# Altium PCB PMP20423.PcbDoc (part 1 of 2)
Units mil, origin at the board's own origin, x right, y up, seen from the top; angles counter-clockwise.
Board outline 2175 x 2115 mil, 4 copper layers (Top Layer, Signal Layer 1, Signal Layer 2, Bottom Layer), stack 82.634 mil thick; 73 components, 45 nets, 246 pads, 105 vias.
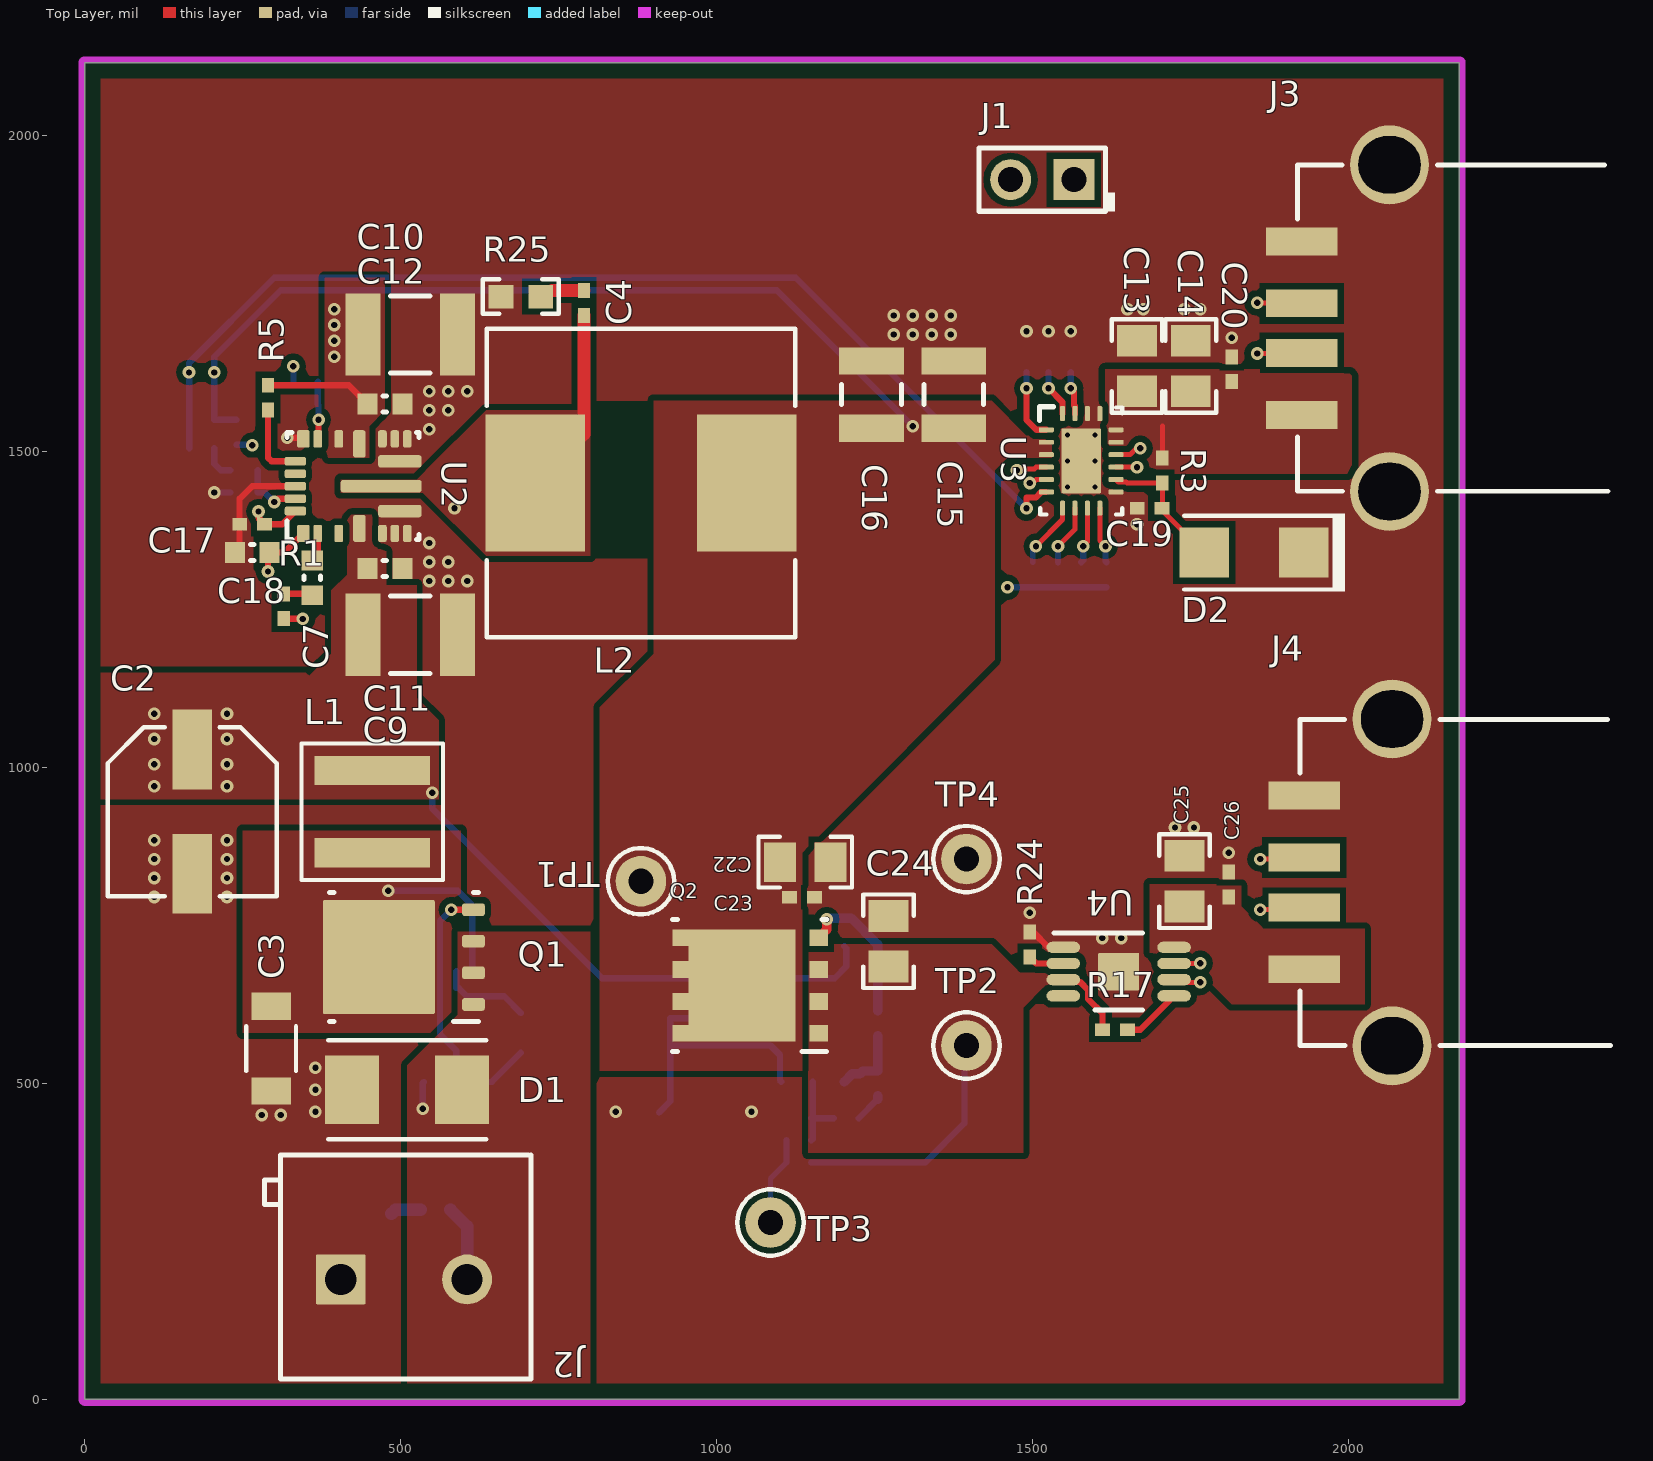
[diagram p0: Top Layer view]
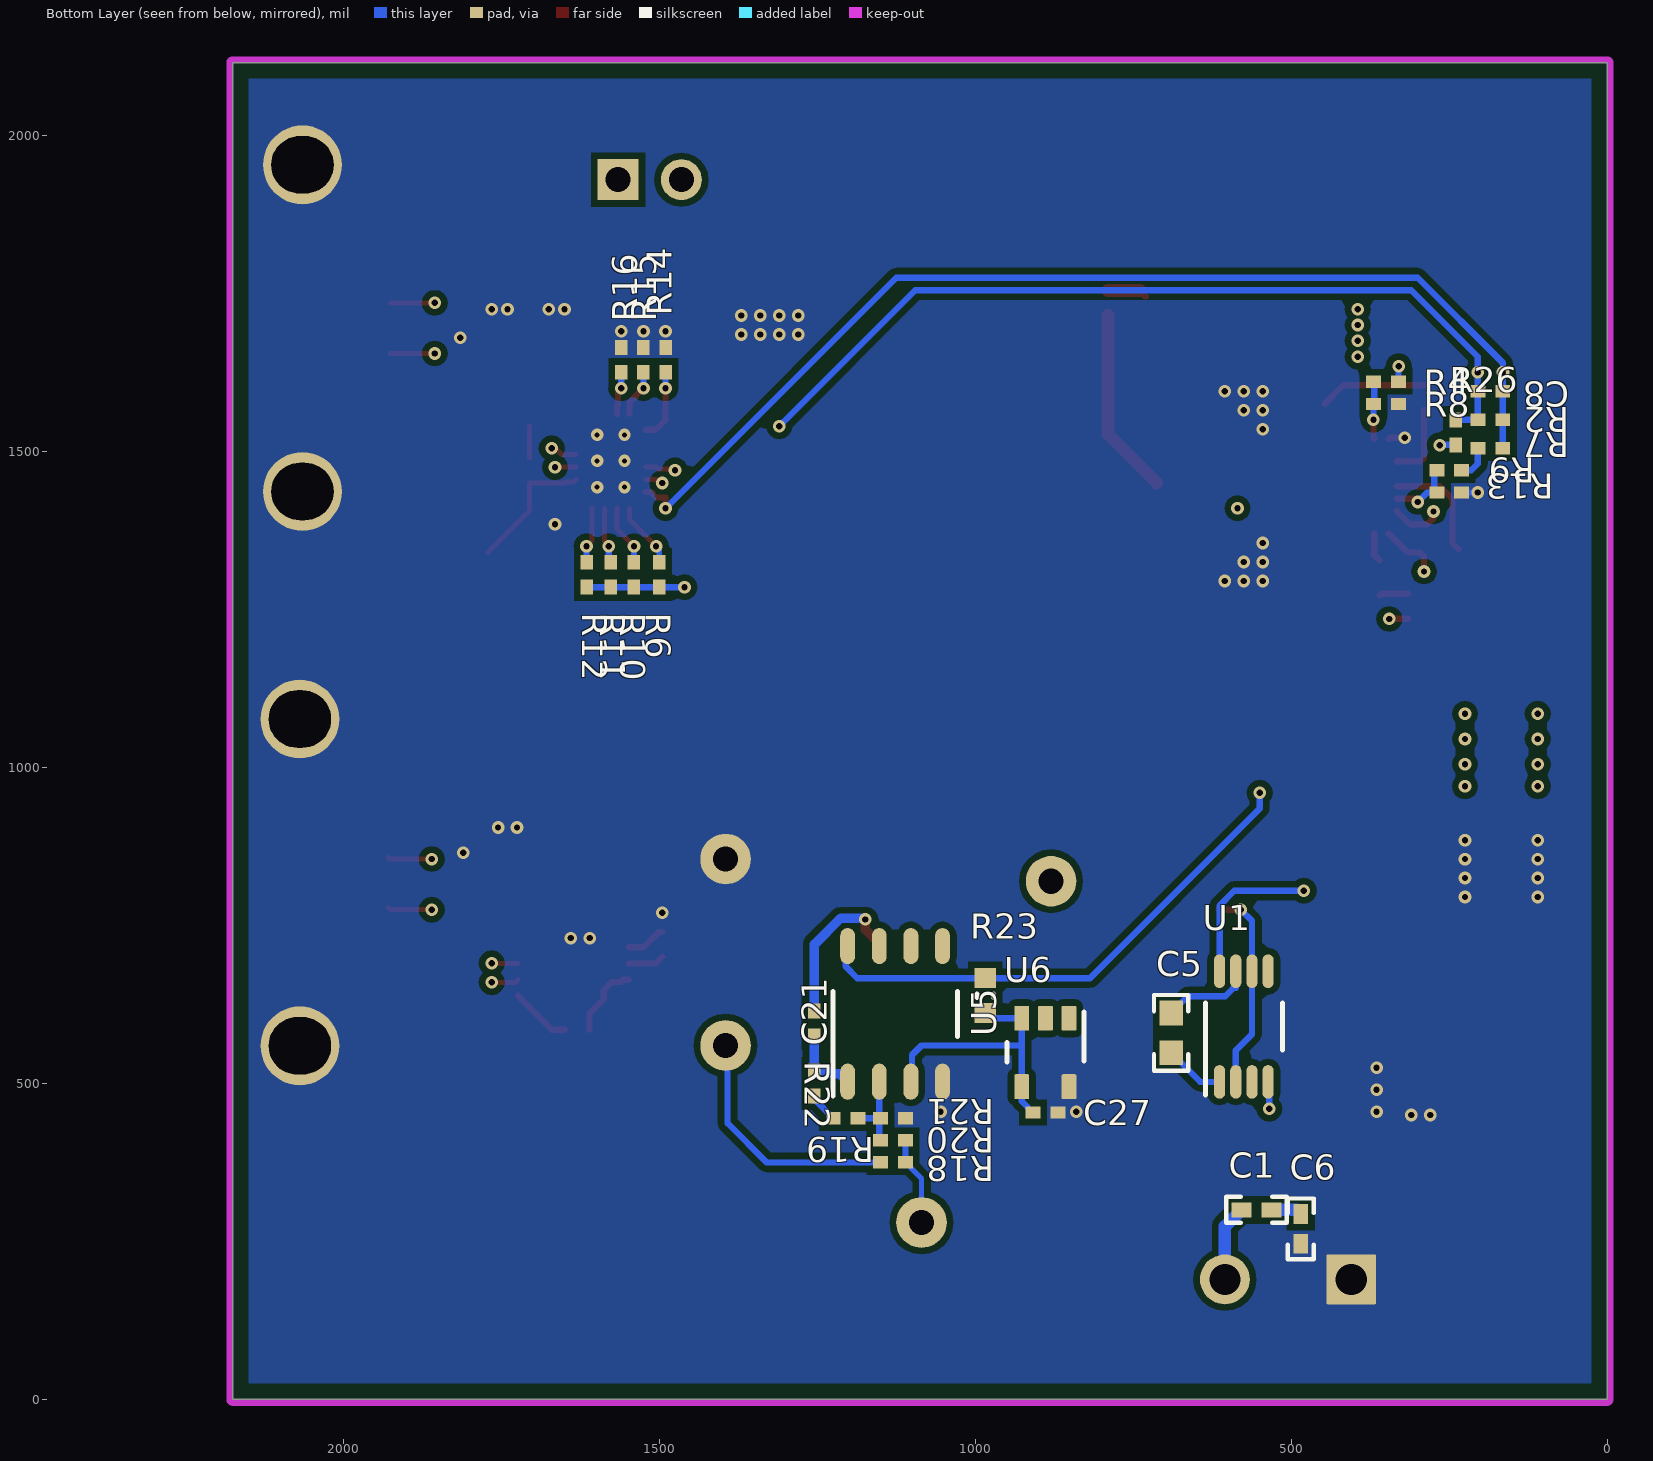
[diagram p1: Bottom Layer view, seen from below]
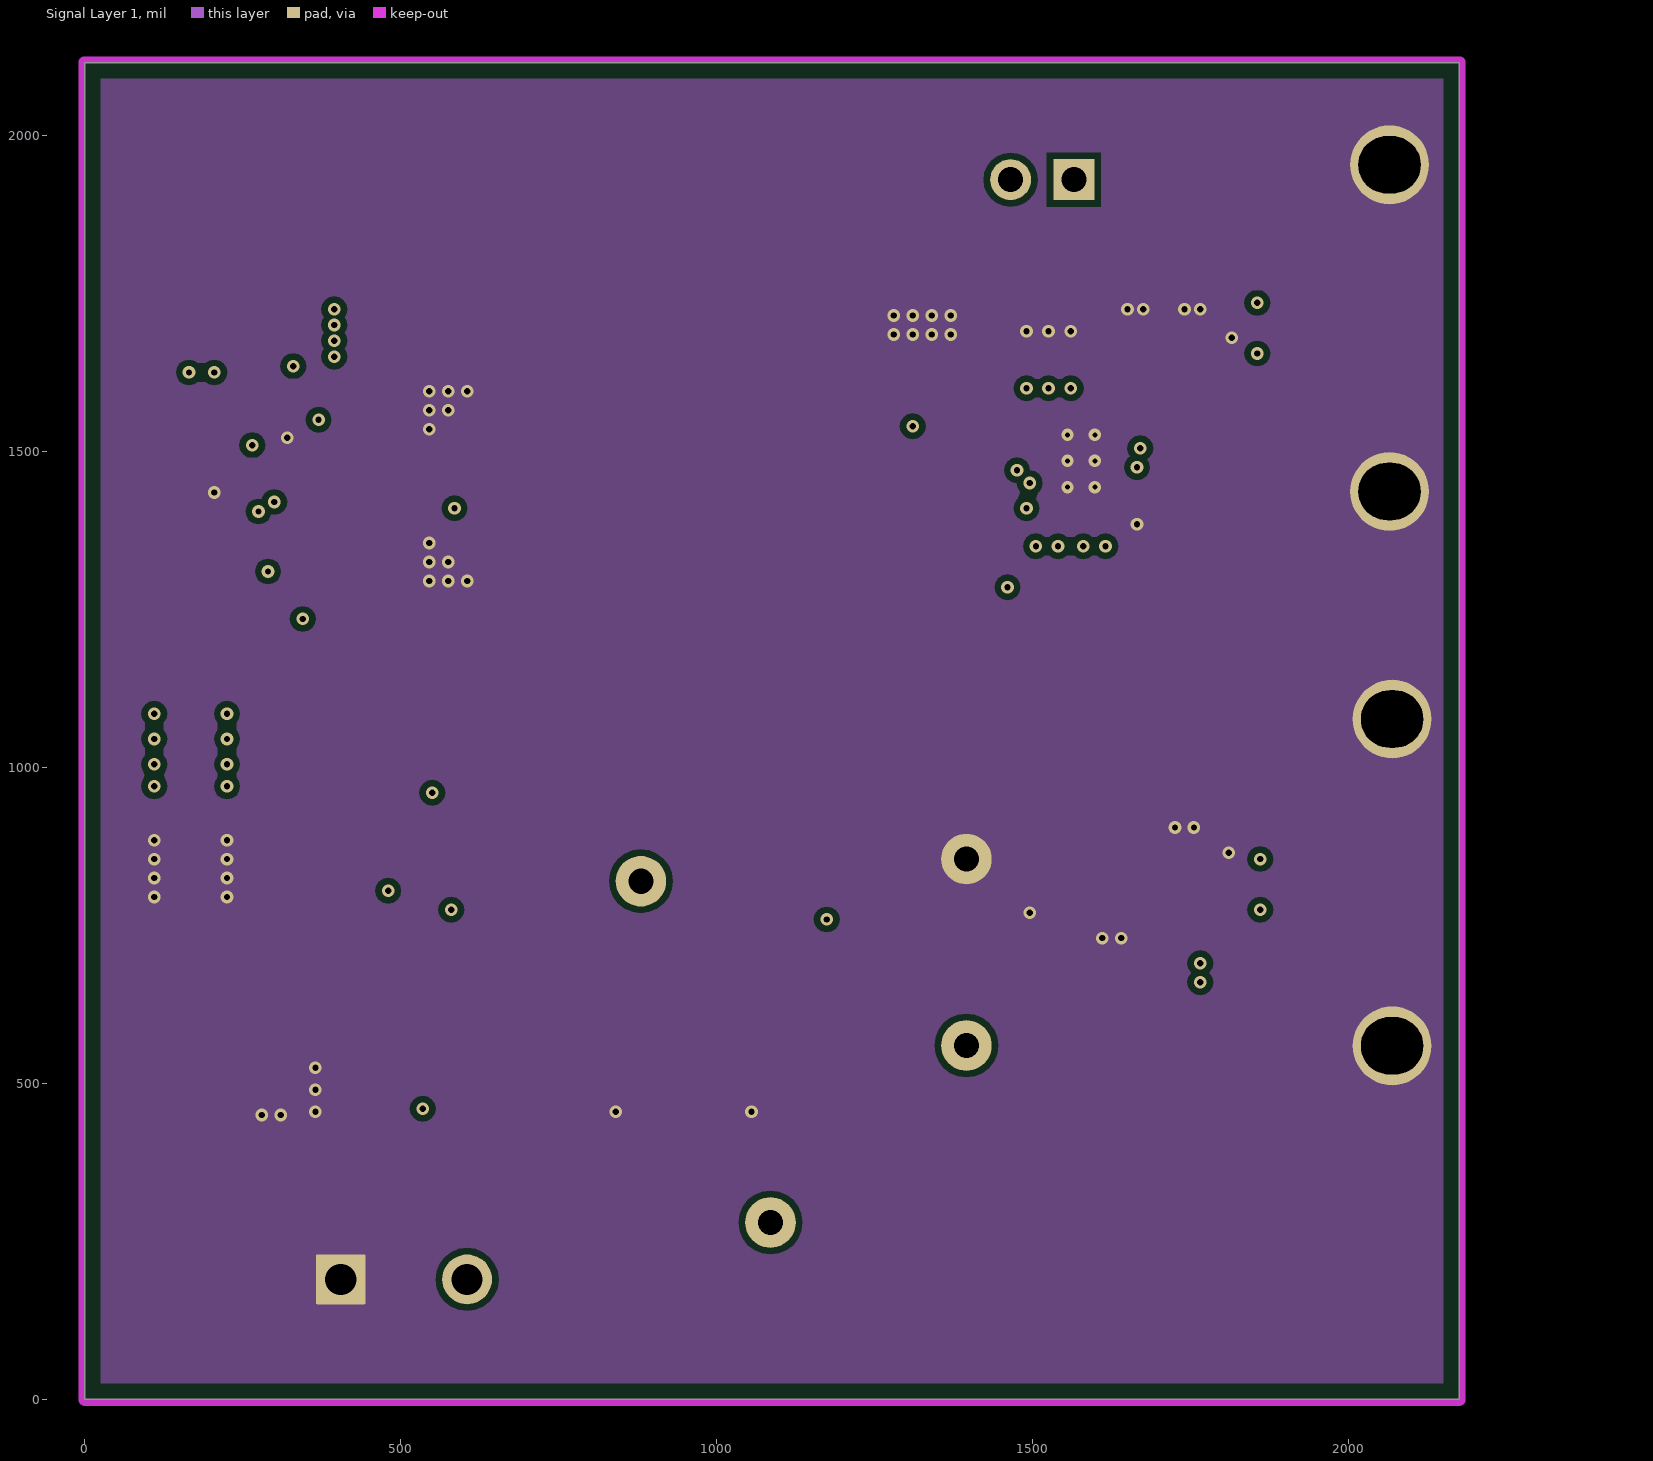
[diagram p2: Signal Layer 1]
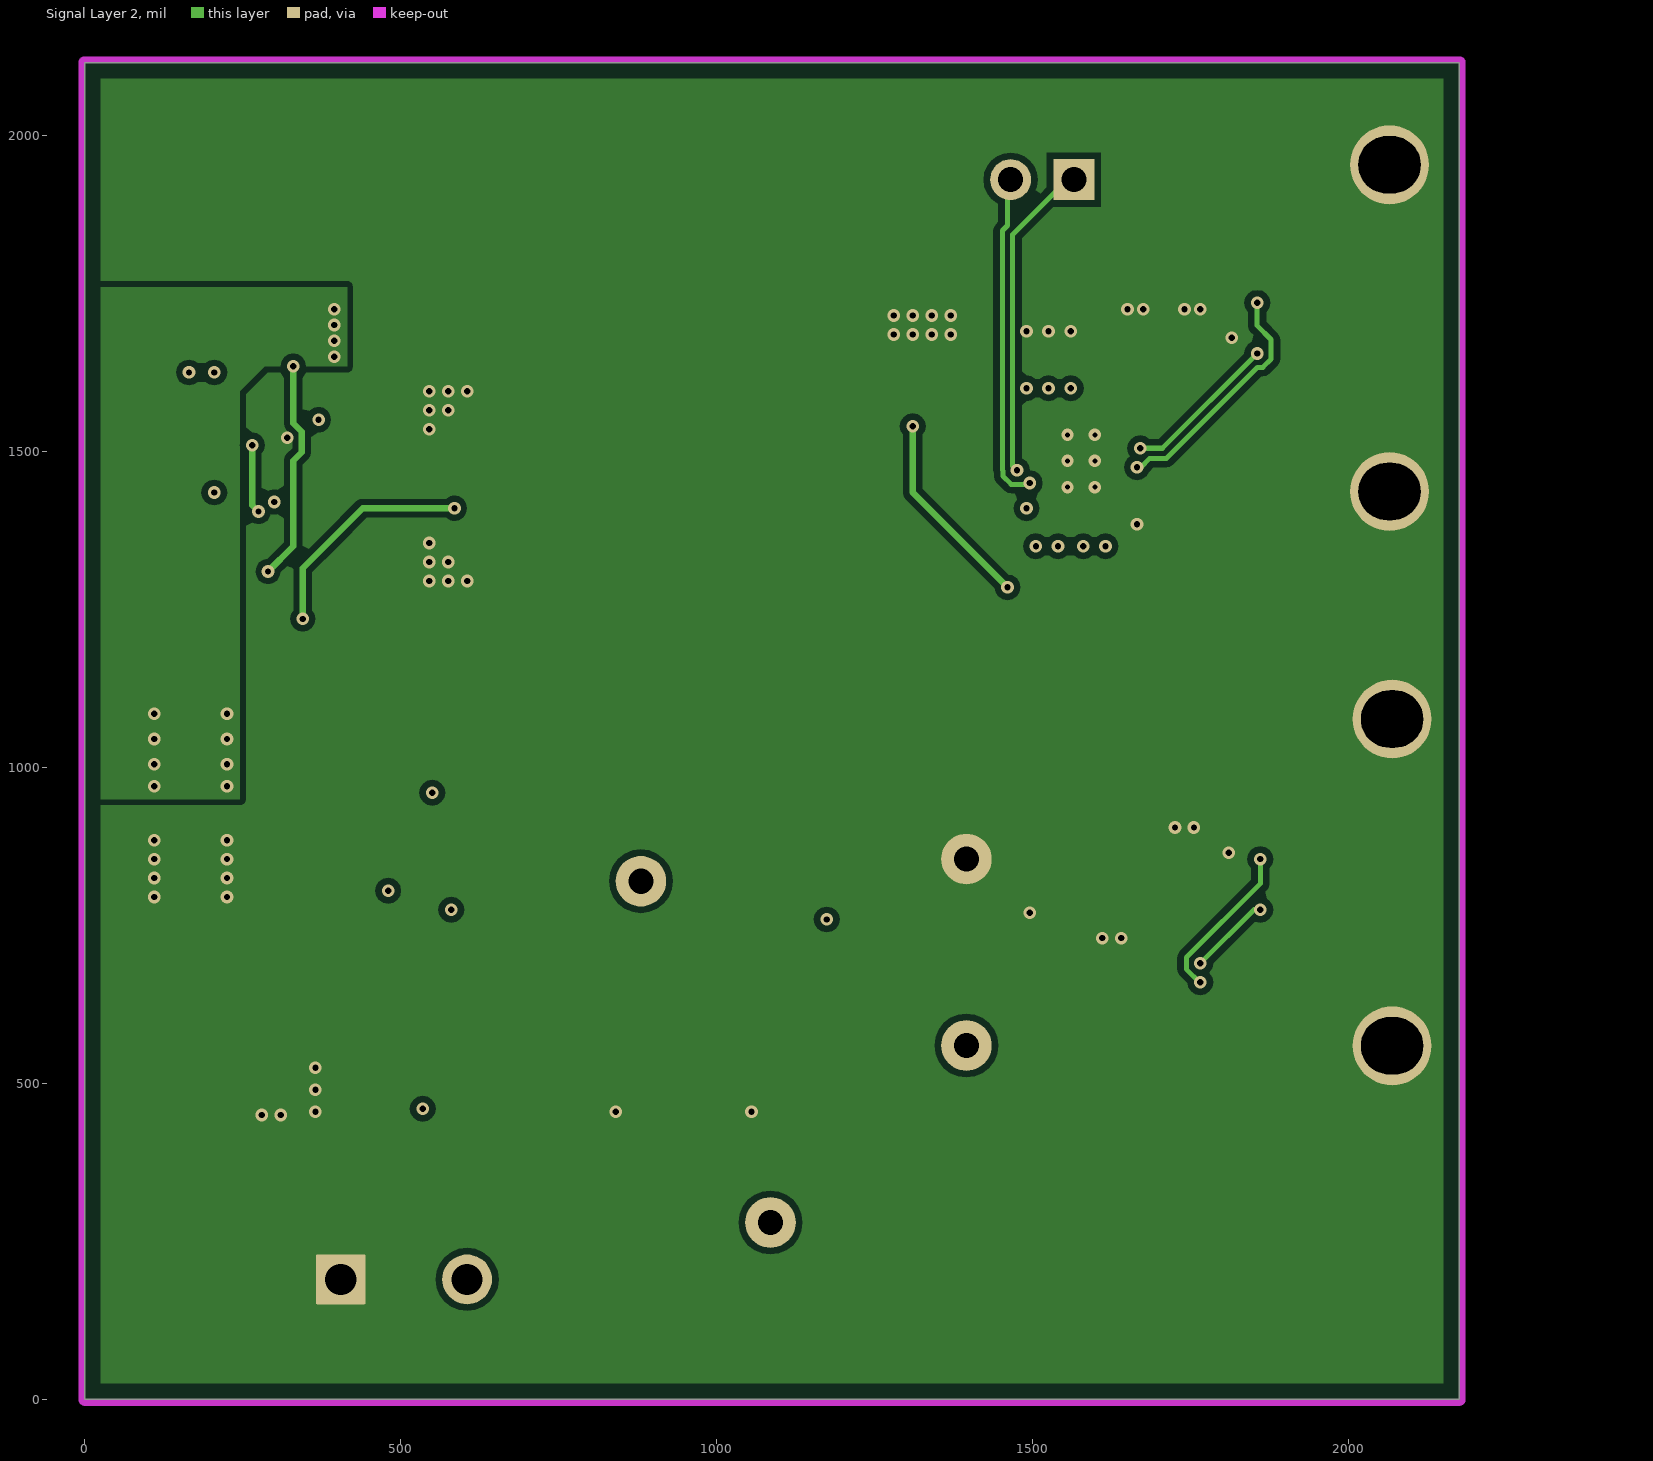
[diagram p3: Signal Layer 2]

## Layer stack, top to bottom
Top Solder: solder mask 0.4, Solder Resist, Dk 3.5
Top Layer: signal copper 2.8
Dielectric1: core 59.2, FR-4, Dk 4.8
Signal Layer 1: signal copper 1.417
Dielectric 3: prepreg 5, Dk 4.2
Signal Layer 2: signal copper 1.417
Dielectric 2: core 10, Dk 4.2
Bottom Layer: signal copper 2.8
Bottom Solder: solder mask 0.4, Solder Resist, Dk 3.5

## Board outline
0,0 2175,0 2175,2115 0,2115

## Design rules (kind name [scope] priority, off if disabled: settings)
AcuteAngle [All] p1: minimum=4.50000000000000E+0001 checktracksonly=FALSE
AssemblyTestPointUsage [All] p1: valid=2
Clearance Clearance_BoardEdge_MountingHoles [OnCopper and InComponentClass('Mounting Holes') vs IsKeepOut] p1: gap=40 ignorepadtopadclearanceinfootprint=FALSE except(0: Arc-Hole Track-Hole SMDPad-Hole THPad-Hole Via-Hole Fill-Hole Poly-Hole Region-Hole Text-Hole)
Clearance Clearance_BoardEdge_Poly [OnCopper and InPoly vs IsKeepOut] p2: gap=25 ignorepadtopadclearanceinfootprint=FALSE except(0: Arc-Hole Track-Hole SMDPad-Hole THPad-Hole Via-Hole Fill-Hole Poly-Hole Region-Hole Text-Hole)
Clearance Clearance_BoardEdge [OnCopper and Not InComponentClass('Logo') and not InComponentClass('FiducialMark') and not InRegion(1000,500,4000,800) and Not IsKeepout vs IsKeepOut] p3: gap=75 ignorepadtopadclearanceinfootprint=FALSE except(0: Arc-Hole Track-Hole SMDPad-Hole THPad-Hole Via-Hole Fill-Hole Poly-Hole Region-Hole Text-Hole)
Clearance Clearance_Poly [InPolygon] p4: gap=10 ignorepadtopadclearanceinfootprint=FALSE except(0: Arc-Hole Track-Hole SMDPad-Hole THPad-Hole Via-Hole Fill-Hole Poly-Hole Region-Hole Text-Hole)
Clearance [All] p5: gap=8 ignorepadtopadclearanceinfootprint=TRUE
ComponentClearance ComponentClearance_ScrewToNut [(HasFootprint('NY PMS 440 0025 PH')) vs (HasFootprint('Keystone_1902C'))] p1: gap=5 collisioncheckmode=3 verticalgap=10 showdistances=FALSE
ComponentClearance ComponentClearance_MountingHoles [InComponentClass('Mounting Holes')] p2: gap=20 collisioncheckmode=3 verticalgap=100000 showdistances=FALSE
ComponentClearance ComponentClearance_SmallPassives [HasFootprint('0201*') or HasFootprint('0402*') or HasFootprint('0508') or HasFootprint('0603*') or HasFootprint('0612') or HasFootprint('0805*') or HasFootprint('0815*') or HasFootprint('0830*') or HasFootprint('1206*') or HasFootprint('1210*') or HasFootprint('1808*') or HasFootprint('1812*') or HasFootprint('1825*') or HasFootprint('2010*') or HasFootprint('2220*') or HasFootprint('2225*') or HasFootprint('2512*') or HasFootprint('2728*') or HasFootprint('3518*') vs HasFootprint('0201*') or HasFootprint('0402*') or HasFootprint('0508') or HasFootprint('0603*') or HasFootprint('0612') or HasFootprint('0805*') or HasFootprint('0815*') or HasFootprint('0830*') or HasFootprint('1206*') or HasFootprint('1210*') or HasFootprint('1808*') or HasFootprint('1812*') or HasFootprint('1825*') or HasFootprint('2010*') or HasFootprint('2220*') or HasFootprint('2225*') or HasFootprint('2512*') or HasFootprint('2728*') or HasFootprint('3518*')] p3: gap=10 collisioncheckmode=3 verticalgap=10 showdistances=FALSE
ComponentClearance ComponentClearance_THtoSMT [IsThruComponent vs IsSMTComponent] p4: gap=20 collisioncheckmode=3 verticalgap=100000 showdistances=FALSE
ComponentClearance ComponentClearance_THtoTH [IsThruComponent vs IsThruComponent] p5: gap=20 collisioncheckmode=3 verticalgap=100000 showdistances=FALSE
ComponentClearance [All] p6: gap=20 collisioncheckmode=3 verticalgap=10 showdistances=FALSE
DiffPairsRouting [All] p1: maxlimit=100 minlimit=10 mostfreqgap=10 toplayer_minwidth=15 toplayer_maxwidth=15 toplayer_prefwidth=15 midlayer1_minwidth=15 midlayer1_maxwidth=15 midlayer1_prefwidth=15 midlayer2_minwidth=15 midlayer2_maxwidth=15 midlayer2_prefwidth=15 bottomlayer_minwidth=15 bottomlayer_maxwidth=15 bottomlayer_prefwidth=15 maxuncoupledlength=1000
FabricationTestPointUsage TestPointUsage [All] p1: valid=2 allowmultiple=FALSE
FabricationTestpoint Testpoint [All] p1: side=3 testpointundercomponent=TRUE minsize=40 maxsize=100 preferedsize=60 minholesize=0 maxholesize=40 preferedholesize=32 testpointgrid=1 allowsidetop=TRUE allowsidebottom=TRUE usegrid=TRUE gridtolerance=0.01
FanoutControl Fanout_LCC [IsLCC] p1: bgadir=Out bgaviamode=Centered fanoutstyle=Auto fanoutdirection=Alternating viagrid=1 // Fanout_LCC (Default Rule)
FanoutControl Fanout_BGA [IsBGA] p2: bgadir=Out bgaviamode=Centered fanoutstyle=Auto fanoutdirection=Alternating viagrid=1 // Fanout_BGA (Default Rule)
FanoutControl Fanout_Default [All] p4: bgadir=Out bgaviamode=Centered fanoutstyle=Auto fanoutdirection=Alternating viagrid=1 // Fanout_Default (Default Rule)
FanoutControl Fanout_Small [(CompPinCount < 5)] p5: bgadir=Out bgaviamode=Centered fanoutstyle=Auto fanoutdirection=OutThenIn viagrid=1 // Fanout_Small (Default Rule)
HoleSize [All] p1: absolutevalues=TRUE maxlimit=251 minlimit=7 maxpercent=80.000 minpercent=20.000
MinimumAnnularRing [All] p1: minimumring=5
MinimumSolderMaskSliver MinimumSolderMaskSliver_Logo [InComponentClass('Logo') vs InComponentClass('Logo')] p1: minsoldermaskwidth=0
MinimumSolderMaskSliver SilkscreenOverComponentPads [All] p2: minsoldermaskwidth=0
MinimumSolderMaskSliver [All] p3: minsoldermaskwidth=0
PlaneConnect [All] p1: planeconnectstyle=Direct reliefexpansion=10 reliefentries=4 reliefconductorwidth=10 reliefairgap=10
PolygonConnect [All] p1: connectstyle=Direct reliefconductorwidth=10 reliefentries=4 polygonreliefangle="90 Angle" airgapwidth=10
RoutingVias [All] p1: holewidth=16 width=34 viastyle="Through Hole" minholewidth=7 minwidth=19 maxholewidth=40 maxwidth=65
SMDToCorner [All] p1: distance=0
SilkToBoardRegionClearance [Not ((IsComment or IsDesignator) And (Hide <> 'False')) and not InRegion(1000,500,4000,800)] p1:
SilkToSilkClearance [All] p1: silktosilkclearance=0
SilkToSolderMaskClearance [IsPad] p1: minsilkscreentomaskgap=0 clearancetoexposedcopper=TRUE
SolderMaskExpansion [All] p1: expansion=3
Width [All] p1: maxlimit=100 minlimit=6 preferedwidth=10 checkconnectedcopper=TRUE
15 further rules are at their usual default settings.

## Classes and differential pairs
component class Header: J1

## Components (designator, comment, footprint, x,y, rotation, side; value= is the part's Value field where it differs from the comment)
C1 "C1005X7R1H104K050BB" 0402 555,300 r180 bottom value=0.1uF
C2 "EEE-FK1V680XP" SM_RADIAL_D8 170,930 r270 top value=68uF
C3 "GRM31CR61H106KA12L" 1206_180 295,555 r270 top value=10uF
C4 "GRM155R71H331KA01D" 0402L 790,1735 r90 top value=330pF
C5 "GRM188R61A225KE34D" 0603 690,580 r270 bottom value=2.2uF
C6 "C1005X7R1H104K050BB" 0402 485,270 r270 bottom value=0.1uF
C7 "GRM188R71E474KA12D" 0603L 360,1300 r90 top value=0.47uF
C8 "GRM155R61C273KA01D" 0402L 185,1595 r180 bottom value=0.027uF
C9 "C4532X7R1E226M250KC" 1812_280L 515,1210 r0 top value=22uF
C10 "C4532X7R1E226M250KC" 1812_280L 515,1685 r0 top value=22uF
C11 "C1608X7R1H224K080AB" 0603L 475,1315 r0 top value=0.22uF
C12 "C1608X7R1H224K080AB" 0603L 475,1575 r0 top value=0.22uF
C13 "GCM21BR70J106KE22L" 0805_HV 1665,1635 r90 top value=10uF
C14 "GCM21BR70J106KE22L" 0805_HV 1750,1635 r90 top value=10uF
C15 "GRM32ER61A107ME20L" 1210_270L 1375,1590 r90 top value=100uF
C16 "GRM32ER61A107ME20L" 1210_270L 1245,1590 r90 top value=100uF
C17 "C1005X7R1H104K050BB" 0402L 265,1385 r0 top value=0.1uF
C18 "GRM188Z71C475KE21D" 0603L 265,1340 r180 top value=4.7uF
C19 "C1005X7R1H104K050BB" 0402L 1685,1410 r180 top value=0.1uF
C20 "C1005X7R1H104K050BB" 0402L 1815,1630 r90 top value=0.1uF
C21 "C1005X7R1H104K050BB" 0402L 1255,500 r270 bottom value=0.1uF
C22 "GRM21BR61C106KE15L" 0805_HV 1140,850 r0 top value=10uF
C23 "C1005X7R1H104K050BB" 0402L 1135,794.66 r0 top value=0.1uF
C24 "GRM21BR61C106KE15L" 0805_HV 1271.86,725 r90 top value=10uF
C25 "GCM21BR70J106KE22L" 0805_HV 1740,820 r90 top value=10uF
C26 "C1005X7R1H104K050BB" 0402L 1810,815 r90 top value=0.1uF
C27 "GRM155R61H102KA01D" 0402L 889.06,454 r180 bottom value=1000pF
D1 "1SMB30CAT3G" SMB-Bi 510,490 r0 top value=30V
D2 "SMAJ16CA" SMA 1850,1340 r180 top value=16V
J1 "5-146278-2" TE_5-146278-2 1515,1930 r180 top
J2 "ED120/2DS" On-Shore_ED120_2DS 505,190 r0 top
J3 "896-43-004-00-000000" CONN_USB_896-43-004-00-000000 1995,1695 r90 top
J4 "896-43-004-00-000000" CONN_USB_896-43-004-00-000000 1999,818 r90 top
L1 "XAL5030-472MEB" XAL5030 455,930 r90 top value=4.7uH
L2 "MSS1278-103MLB" MSS1278 880,1450 r0 top value=10uH
Q1 "CSD18563Q5A" DQJ0008A 505,700 r180 top value=60V
Q2 "CSD16408Q5C" TRANS_NexFET_Q5C 1051.86,655 r180 top value=25V
R1 "CRCW04020000Z0ED" 0402L 315,1255 r90 top value=0
R2 "CRCW04022K67FKED" 0402L 185,1550 r0 bottom value=2.67k
R3 "CRCW04025K11FKED" 0402L 1705,1470 r90 top value=5.11k
R4 "CRCW04020000Z0ED" 0402L 350,1610 r180 bottom value=0
R5 "CRCW0402100KJNED" 0402L 290,1585 r270 top value=100k
R6 "CRCW04020000Z0ED" 0402L 1500,1305 r270 bottom value=0
R7 "CRCW04020000Z0ED" 0402L 185,1505 r180 bottom value=0
R8 "CRCW04020000Z0ED" 0402L 350,1575 r0 bottom value=0
R9 "CRCW040237K4FKED" 0402L 250,1470 r180 bottom value=37.4k
R10 "CRCW0402100KJNED" 0402L 1540,1305 r270 bottom value=100k
R11 "CRCW0402100KJNED" 0402L 1576.65,1305 r270 bottom value=100k
R12 "CRCW0402100KJNED" 0402L 1615,1305 r270 bottom value=100k
R13 "CRCW040210K0FKED" 0402L 250,1435 r0 bottom value=10.0k
R14 "CRCW04022K55FKED" 0402L 1490,1645 r270 bottom value=2.55k
R15 "CRCW040219K1FKED" 0402L 1525,1645 r270 bottom value=19.1k
R16 "CRCW040219K1FKED" 0402L 1560,1645 r270 bottom value=19.1k
R17 "CRCW04020000Z0ED" 0402L 1630,585 r180 top value=0
R18 "CRCW040249R9FKED" 0402L 1130,375 r0 bottom value=49.9
R19 "CRCW04020000Z0ED" 0402L 1205,445 r0 bottom value=0
R20 "CRCW040221K0FKED" 0402L 1130,410 r180 bottom value=21.0k
R21 "CRCW040220K0FKED" 0402L 1130,445 r0 bottom value=20.0k
R22 "CRCW04020000Z0ED" 0402L 1255,595 r90 bottom value=0
R23 "CRCW06032K00FKEA" 0603L 984.06,639 r90 bottom value=2.00k
R24 "CRCW040220K5FKED" 0402L 1495,720 r270 top value=20.5k
R25 "CRCW060320R0JNEA" 0603 690,1745 r0 top value=20
R26 "CRCW04020000Z0ED" 0402L 240,1530 r270 bottom value=0
TP1 "5000" Keystone5000 880,820 r270 top
TP2 "5000" Keystone5000 1395,560 r270 top
TP3 "5002" Keystone5002 1085,280 r90 top
TP4 "5001" Keystone5001 1395,855 r270 top
U1 "LM74610QDGKRQ1" DGK0008A_N 575,590 r90 bottom
U2 "LMS3655AQRNLRQ1" RNL0022A_NV 424.72,1445 r90 top
U3 "TPS254900IRVCRQ1" RVC0020A 1576.65,1485 r0 top
U4 "TPS2511DGNR" DGN0008E_N 1636,677 r0 top
U5 "LM358AD" D0008A_N 1126.86,610 r90 bottom
U6 "TL431ACDBVRG4A" DBV0005A_N 889.06,549 r270 bottom

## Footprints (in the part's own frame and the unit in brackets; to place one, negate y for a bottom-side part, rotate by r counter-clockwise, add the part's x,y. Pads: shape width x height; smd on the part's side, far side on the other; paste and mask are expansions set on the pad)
0402 [mm] "0402 from SM-752 data"
  rect 0.8x0.6 smd: 1(-0.6,0) 2(0.6,0)
  silkscreen extent -1.22,-0.52 1.22,0.52, body extent -0.55,-0.3 0.55,0.3, height 0.6
0402L [mm] "0402 from SM-752 data"
  rect 0.6x0.5 smd: 1(-0.5,0) 2(0.5,0)
  body extent -0.55,-0.3 0.55,0.3, height 0.6
0603 [mm] "0603 from SM-752 data"
  rect 1x0.95 smd: 1(-0.8,0) 2(0.8,0)
  silkscreen extent -1.52,-0.69 1.52,0.69, body extent -0.87,-0.47 0.87,0.47, height 1
0603L [mm] "0603 from SM-752 data"
  rect 0.8x0.85 smd: 1(-0.7,0) 2(0.7,0)
  silkscreen extent -0.07,-0.33 0.07,0.33, body extent -0.87,-0.47 0.87,0.47, height 1
0805_HV [mil] "0805 with 30mil clearance between pads"
  rect 50x63 smd: 1(-40,0) 2(40,0)
  silkscreen extent -74,-40 74,40, body extent -43,-29 43,29, height 57
1206_180 [mm] "1206_180"
  rect 1.1x1.6 smd: 1(-1.7,0) 2(1.7,0)
  silkscreen extent -0.9,-1 0.9,1, body extent -1.75,-0.95 1.75,0.95, height 1.8
1210_270L [mm] "1210"
  rect 1.1x2.6 smd: 1(-1.35,0) 2(1.35,0)
  silkscreen extent -0.4,-1.2 0.4,1.2, body extent -1.7,-1.35 1.7,1.35, height 2.7
1812_280L [mm] "1812"
  rect 1.4x3.3 smd: 1(-1.9,0) 2(1.9,0)
  silkscreen extent -0.8,-1.55 0.8,1.55, body extent -2.4,-1.7 2.4,1.7, height 2.8
CONN_USB_896-43-004-00-000000 [mm] "MILLMAX"
  rect 1.12x2.87 smd: 1(-3.49,1.768) 2(-1,1.768) 3(1,1.768) 4(3.49,1.768)
  round 3.17 hole 2.3 slot 2.5 at 90 deg: 5(-6.565,-1.767) 6(6.565,-1.767)
  silkscreen extent -6.55,-10.54 6.55,1.93, body extent -6.55,-12.07 6.55,1.92, height 6.99
D0008A_N [mm] "SOIC, 8-Leads, Body 4.9x3.9mm, Pitch 1.27mm, IPC Medium Density"
  oval 1.45x0.6 smd: 1(-2.725,1.905) 2(-2.725,0.635) 3(-2.725,-0.635) 4(-2.725,-1.905) 5(2.725,-1.905) 6(2.725,-0.635) 7(2.725,0.635) 8(2.725,1.905)
  silkscreen extent -3.3,-2.5 0.9,2.5, body extent -3,-2.45 3,2.45, height 1.63
DBV0005A_N [mm] "SOT23, 5-Leads, Body 2.9x1.6mm, Pitch 0.95mm, Lead Span 2.8mm, IPC Medium Density"
  rrect17% 1x0.6 smd: 1(-1.375,0.95) 2(-1.375,0) 3(-1.375,-0.95) 4(1.375,-0.95) 5(1.375,0.95)
  silkscreen extent -1.63,-1.55 0.38,1.55, body extent -1.42,-1.46 1.42,1.46, height 1.09
DGK0008A_N [mm] "TSOP, 8-Leads, Body 3x3mm, Pitch 0.65mm, IPC Medium Density"
  oval 1.35x0.45 smd: 1(-2.225,0.975) 2(-2.225,0.325) 3(-2.225,-0.325) 4(-2.225,-0.975) 5(2.225,-0.975) 6(2.225,-0.325) 7(2.225,0.325) 8(2.225,0.975)
  silkscreen extent -2.75,-1.55 0.95,1.55, body extent -2.45,-1.5 2.45,1.5, height 0.96
DGN0008E_N [mm] "TSOP, 8-Leads, Body 3x3mm, Pitch 0.65mm, Thermal Pad 1.89x1.57mm, IPC Medium Density"
  rrect100% 1.35x0.45 smd: 1(-2.225,0.975) 2(-2.225,0.325) 3(-2.225,-0.325) 4(-2.225,-0.975) 5(2.225,-0.975) 6(2.225,-0.325) 7(2.225,0.325) 8(2.225,0.975)
  rrect7% 1.65x1.51 smd: 9(0,0)
  silkscreen extent -2.6,-1.55 0.95,1.55, body extent -2.46,-1.5 2.46,1.5, height 1.1
DQJ0008A [mm] "SMD, 8-Leads, Body 5.75x4.9mm"
  rrect39% 0.91x0.51 smd paste-0.05 mask-0.05: 1(-2.795,1.905) 2(-2.795,0.635) 3(-2.795,-0.635) 4(-2.795,-1.905) 5(2.795,-1.905) 6(2.795,-0.635) 7(2.795,0.635) 8(2.795,1.905)
  rrect8% 1.58x1.25 on Top Paste: 9(-0.38,1.45) 9(-0.38,0) 9(-0.38,-1.45) 9(1.4,1.45) 9(1.4,0) 9(1.4,-1.45)
  rrect3% 3.48x4.47 on Top Solder: 9(0.55,0)
  rrect2% 4.49x4.57 smd paste-2.5 mask-2.5: 9(1.005,0)
  silkscreen extent -3,-2.6 3,2.6, body extent -3.13,-2.45 3.13,2.45, height 1.15
Keystone5000 [mil] "For Keystone 500x miniature loop terminals"
  round 80 hole 40: 1(0,0)
  silkscreen extent -52,-52 52,52, body extent -49,-49 49,49, height 182
Keystone5001 [mil] "For Keystone 500x miniature loop terminals"
  round 80 hole 40: 1(0,0)
  silkscreen extent -52,-52 52,52, body extent -49,-49 49,49, height 182
Keystone5002 [mil] "For Keystone 500x miniature loop terminals"
  round 80 hole 40: 1(0,0)
  silkscreen extent -52,-52 52,52, body extent -49,-49 49,49, height 182
MSS1278 [mm] "Coilcraft recommended land pattern.  Document 598-2 rev 04/04/13"
  rect 4x5.5 smd: 1(-4.25,0) 2(4.25,0)
  silkscreen extent -6.2,-6.2 6.2,6.2, body extent -6.15,-6.15 6.15,6.15, height 8.05
On-Shore_ED120_2DS [mm] "ONSHORE"
  rrect5% 2x2 hole 1.25: 1(-2.54,0)
  round 2 hole 1.25: 2(2.54,0)
  silkscreen extent -5.6,-4 5.12,5, body extent -5.78,-4 5.08,5, height 13
RNL0022A_NV [mm] "VQFN, 22 pin, 0.5 mm pitch"
  rrect25% 0.7x0.5 smd paste-0.05 mask-0.05: 1(-1.9,2) 17(1.9,2)
  rrect40% 0.7x0.35 smd paste-0.05 mask-0.05: 2(-1.9,1.425) 3(-1.9,0.575) 15(1.9,0.575) 16(1.9,1.425)
  rrect40% 1.1x0.5 smd paste-0.25 mask-0.05: 4(-1.7,-0.25) 14(1.7,-0.25)
  rrect25% 0.4x0.4 on Top Paste: 4A(-2,-0.25) 4B(-1.4,-0.25) 14A(1.4,-0.25) 14B(2,-0.25)
  rrect57% 0.7x0.35 smd paste-0.05 mask-0.05: 5(-1.9,-1.175) 6(-1.9,-1.675) 7(-1.9,-2.175) 11(1.9,-2.175) 12(1.9,-1.675) 13(1.9,-1.175)
  rrect40% 0.5x1.74 smd paste-0.25 mask-0.05: 8(-1,-1.875) 10(1,-1.875)
  rrect25% 0.4x0.66 on Top Paste: 8A(-1,-1.445) 8B(-1,-2.305) 10A(1,-1.445) 10B(1,-2.305)
  rrect40% 0.5x3.25 smd paste-0.25 mask-0.05: 9(0,-1.125)
  rrect25% 0.4x0.63 on Top Paste: 9A(0,0.12) 9B(0,-0.71) 9C(0,-1.54) 9D(0,-2.37)
  rrect40% 0.35x0.85 smd paste-0.05 mask-0.05: 18(1,2.325) 19(0.5,2.325) 20(0,2.325) 21(-0.5,2.325) 22(-1,2.325)
  silkscreen extent -2.15,-2.65 2.15,2.65, body extent -2,-2.5 2,2.5, height 0.9
RVC0020A [mm] "TI"
  rrect50% 0.6x0.2 smd: 1(-1.4,1.25) 2(-1.4,0.75) 3(-1.4,0.25) 4(-1.4,-0.25) 5(-1.4,-0.75) 6(-1.4,-1.25) 11(1.4,-1.25) 12(1.4,-0.75) 13(1.4,-0.25) 14(1.4,0.25) 15(1.4,0.75) 16(1.4,1.25)
  rrect50% 0.2x0.6 smd: 7(-0.75,-1.9) 8(-0.25,-1.9) 9(0.25,-1.9) 10(0.75,-1.9) 17(0.75,1.9) 18(0.25,1.9) 19(-0.25,1.9) 20(-0.75,1.9)
  rrect9% 1.47x1.15 on Top Paste: 21(0,-0.675) 21(0,0.675)
  rrect6% 1.6x2.6 smd paste-1: 21(0,0)
  silkscreen extent -1.68,-2.15 1.65,2.18, body extent -1.5,-2 1.5,2, height 0.8
SM_RADIAL_D8 [mm] "6.3 x 7.7mm:  Panasonic D8"
  rect 3.2x1.6 smd: 1(-2.5,0) 2(2.5,0)
  silkscreen extent -3.4,-3.4 3.4,3.4, body extent -3.4,-3.4 3.4,3.4, height 8.01
SMA [mm] "Molded Diode, 2-Leads, Body 4.3x2.6mm, IPC Medium Density, based on OnSemi component dimensions and land pattern"
  rect 2x2 smd: 1(-2,0) 2(2,0)
  silkscreen extent -3.66,-1.57 2.79,1.57, body extent -2.6,-1.3 2.6,1.3, height 2.42
SMB-Bi [mil] "Molded Diode, 2-Leads, Body 5.4x3.6mm, IPC Medium Density, based on OnSemi component dimensions"
  rect 85x107.99 smd: 1(-87.01,0) 2(87.01,0)
  silkscreen extent -125,-79 125,79, body extent -104,-73 104,73, height 89
TE_5-146278-2 [mm] "TE CONNECTIVITY"
  rect 1.65x1.65 hole 1: 1(-1.27,0)
  round 1.65 hole 1: 2(1.27,0)
  silkscreen extent -2.92,-1.27 2.54,1.27, body extent -2.41,-1.17 2.41,1.17, height 8.13
TRANS_NexFET_Q5C [mm] "TI recommended land pattern (nominal) M0139-01"
  rect 0.75x0.675 smd mask+0.051: 1(-2.776,1.917) 2(-2.776,0.639) 3(-2.776,-0.639) 4(-2.776,-1.917)
  rect 0.655x0.675 smd mask+0.051: 5(2.776,-1.917) 6(2.776,-0.639) 7(2.776,0.639) 8(2.776,1.917)
  rect 4.295x4.51 smd paste-2.2 mask+0.051: 10(0.301,0)
  silkscreen extent -3.11,-2.66 3.1,2.65, body extent -3.05,-2.55 3.05,2.55, height 1.06
XAL5030 [mil] "Coilcraft XAL5030 12/12/11"
  rect 46x183 smd: 1(-65,0) 2(65,0)
  silkscreen extent -108,-112 108,112, body extent -108,-112 108,112, height 122

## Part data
C1 C6 C17 C19 C20 C21 C23 C26: "CAP, CERM, 0.1 µF, 50 V, +/- 10%, X7R, 0402", Cap_Case=0402, Manufacturer=TDK, Supplier Part Number 1=445-5932-1-ND, TempCo=X7R, Tolerance_%=10, Value1="0.039064 ohm", Value2=50V, ValueDisplayed=0.1µF
C2: "CAP, AL, 68 µF, 35 V, +/- 20%, 0.34 ohm, AEC-Q200 Grade 2, SMD", Cap_Case=D8, Manufacturer=Panasonic, Supplier Part Number 1=PCE3844CT-ND, Tolerance_%=20, Value1="0.34 ohm", Value2=35V, ValueDisplayed=68µF
C3: "CAP, CERM, 10 µF, 50 V, +/- 10%, X5R, 1206", Cap_Case=1206, Manufacturer=MuRata, Supplier Part Number 1=490-5961-1-ND, TempCo=X5R, Tolerance_%=10, Value1=Unknown, Value2=50V, ValueDisplayed=10µF
C4: "CAP, CERM, 330 pF, 50 V,+/- 10%, X7R, 0402", Cap_Case=0402, Manufacturer=MuRata, Supplier Part Number 1=490-3247-1-ND, TempCo=X7R, Tolerance_%=10, Value1=Unknown, Value2=50V, ValueDisplayed=DNP
C5: "CAP, CERM, 2.2 µF, 10 V, +/- 10%, X5R, 0603", Cap_Case=0603, Manufacturer=MuRata, Supplier Part Number 1=490-1545-1-ND, TempCo=X5R, Tolerance_%=10, Value1=Unknown, Value2=10V, ValueDisplayed=2.2µF
C7: "CAP, CERM, 0.47 µF, 25 V,+/- 10%, X7R, 0603", Cap_Case=0603, Manufacturer=MuRata, Supplier Part Number 1=490-3291-1-ND, TempCo=X7R, Tolerance_%=10, Value1=Unknown, Value2=25V, ValueDisplayed=0.47µF
C8: "CAP, CERM, 0.027 µF, 16 V,+/- 10%, X5R, 0402", Cap_Case=0402, Manufacturer=MuRata, Supplier Part Number 1=GRM155R61C273KA01D-ND, TempCo=X5R, Tolerance_%=10, Value1=Unknown, Value2=16V, ValueDisplayed=0.027µF
C9 C10: "CAP, CERM, 22 µF, 25 V,+/- 20%, X7R, 1812", Cap_Case=1812, Manufacturer=TDK, Supplier Part Number 1=445-1607-1-ND, TempCo=X7R, Tolerance_%=20, Value1="0.002434 ohm", Value2=25V, ValueDisplayed=22µF
C11 C12: "CAP, CERM, 0.22 µF, 50 V,+/- 10%, X7R, 0603", Cap_Case=0603, Manufacturer=TDK, Supplier Part Number 1=445-7408-1-ND, TempCo=X7R, Tolerance_%=10, Value1="0.021699 ohm", Value2=50V, ValueDisplayed=0.22µF
C13 C14 C25: "CAP, CERM, 10 µF, 6.3 V, +/- 10%, X7R, 0805", Cap_Case=0805, Manufacturer=MuRata, Supplier Part Number 1=490-5319-1-ND, TempCo=X7R, Tolerance_%=10, Value1=Unknown, Value2=6.3V, ValueDisplayed=10µF
C15 C16: "CAP, CERM, 100 µF, 10 V,+/- 20%, X5R, 1210", Cap_Case=1210, Manufacturer=MuRata, Supplier Part Number 1=490-9969-1-ND, TempCo=X5R, Tolerance_%=20, Value1=Unknown, Value2=10V, ValueDisplayed=100µF
C18: "CAP, CERM, 4.7 µF, 16 V,+/- 10%, X7R, 0603", Cap_Case=0603, Manufacturer=MuRata, TempCo=X7R, Tolerance_%=10, Value1=Unknown, Value2=16V, ValueDisplayed=4.7µF
C22 C24: "CAP, CERM, 10 µF, 16 V,+/- 10%, X5R, 0805", Cap_Case=0805, Manufacturer=MuRata, Supplier Part Number 1=490-3886-1-ND, TempCo=X5R, Tolerance_%=10, Value1="0.008 ohm", Value2=16V, ValueDisplayed=10µF
C27: "CAP, CERM, 1000 pF, 50 V, +/- 10%, X5R, 0402", Cap_Case=0402, Manufacturer=MuRata, Supplier Part Number 1=GRM155R61H102KA01D-ND, TempCo=X5R, Tolerance_%=10, Value1=Unknown, Value2=50V, ValueDisplayed=1000pF
D1: "Diode, TVS, Bi, 30 V, 600 W, SMB", Manufacturer="ON Semiconductor", Power_W=600, Supplier Part Number 1=1SMB30CAT3GOSCT-ND, Value1=600W
D2: "Diode, TVS, Bi, 16 V, 400 W, SMA", Manufacturer=Littelfuse, Power_W=400, Supplier Part Number 1=SMAJ16CALFDKR-ND, Value1=400W
J1: "Header, 100mil, 2x1, Tin, TH", Manufacturer="TE Connectivity", Supplier Part Number 1=5-146278-2-ND
J2: "Terminal Block, 5.08 mm, 2x1, Brass, TH", Color=Blue, Current_A=15, Manufacturer="On-Shore Technology", Supplier Part Number 1=ED1609-ND, Voltage_V=300
J3 J4: "Connector, Receptacle, USB TYPE A, R/A, Top Mount SMT", Color=Silver, Current_A=1, Manufacturer=Mill-Max, Supplier Part Number 1=ED90065-ND, Voltage_V=30
L1: "Inductor, Shielded, Composite, 4.7 µH, 5.9 A, 0.04 ohm, SMD", Manufacturer=Coilcraft, Value1="0.04 ohm", Value2=5.9A, ValueDisplayed=4.7µH
L2: "Inductor, Shielded Drum Core, Ferrite, 10 µH, 5.7 A, 0.02 ohm, SMD", Manufacturer=Coilcraft, Value1="0.02 ohm", Value2=5.7A, ValueDisplayed=10µH
Q1: "MOSFET, N-CH, 60 V, 15 A, DQJ0008A (VSONP-8)", Alternate Manufacturer=None, Manufacturer="Texas Instruments", Supplier Part Number 1=296-36511-1-ND, Value1="0.0086 ohm", Value2="15 nC"
Q2: "MOSFET, N-CH, 25 V, 113 A, DualCool SON 5x6mm", Alternate Manufacturer=None, Manufacturer="Texas Instruments", Supplier Part Number 1=296-25647-1-ND, Value1="0.0054 ohm", Value2="6.7 nC"
R1 R4 R6 R7 R17 R19 R22 R26: "RES, 0, 5%, 0.063 W, 0402", Manufacturer=Vishay-Dale, Power_W=0.063, Supplier Part Number 1=541-0.0JCT-ND, TempCo="200 ppm/C", Tolerance_%=5, Value1=5%, Value2=0.063W, Value_Code=0000, ValueDisplayed=0
R2: "RES, 2.67 k, 1%, 0.063 W, 0402", Manufacturer=Vishay-Dale, Power_W=0.063, Supplier Part Number 1=541-2.67KLCT-ND, TempCo="100 ppm/C", Tolerance_%=1, Value1=1%, Value2=0.063W, Value_Code=2k67, ValueDisplayed=2.67k
R3: "RES, 5.11 k, 1%, 0.063 W, 0402", Manufacturer=Vishay-Dale, Power_W=0.063, Supplier Part Number 1=541-5.11KLCT-ND, TempCo="100 ppm/C", Tolerance_%=1, Value1=1%, Value2=0.063W, Value_Code=5k11, ValueDisplayed=5.11k
R5 R10 R11 R12: "RES, 100 k, 5%, 0.063 W, 0402", Manufacturer=Vishay-Dale, Power_W=0.063, Supplier Part Number 1=541-100KJCT-ND, TempCo="200 ppm/C", Tolerance_%=5, Value1=5%, Value2=0.063W, Value_Code=100k
R8: "RES, 0, 5%, 0.063 W, 0402", Manufacturer=Vishay-Dale, Power_W=0.063, Supplier Part Number 1=541-0.0JCT-ND, TempCo="200 ppm/C", Tolerance_%=5, Value1=5%, Value2=0.063W, Value_Code=0000, ValueDisplayed=DNP
R9: "RES, 37.4 k, 1%, 0.063 W, 0402", Manufacturer=Vishay-Dale, Power_W=0.063, Supplier Part Number 1=541-37.4KLCT-ND, TempCo="100 ppm/C", Tolerance_%=1, Value1=1%, Value2=0.063W, Value_Code=37k4, ValueDisplayed=37.4k
R13: "RES, 10.0 k, 1%, 0.063 W, 0402", Manufacturer=Vishay-Dale, Power_W=0.063, Supplier Part Number 1=541-10.0KLCT-ND, TempCo="100 ppm/C", Tolerance_%=1, Value1=1%, Value2=0.063W, Value_Code=10k0, ValueDisplayed=10.0k
R14: "RES, 2.55 k, 1%, 0.063 W, 0402", Manufacturer=Vishay-Dale, Power_W=0.063, Supplier Part Number 1=541-2.55KLCT-ND, TempCo="100 ppm/C", Tolerance_%=1, Value1=1%, Value2=0.063W, Value_Code=2k55, ValueDisplayed=2.55k
R15 R16: "RES, 19.1 k, 1%, 0.063 W, 0402", Manufacturer=Vishay-Dale, Power_W=0.063, Supplier Part Number 1=541-19.1KLCT-ND, TempCo="100 ppm/C", Tolerance_%=1, Value1=1%, Value2=0.063W, Value_Code=19k1, ValueDisplayed=19.1k
R18: "RES, 49.9, 1%, 0.063 W, 0402", Manufacturer=Vishay-Dale, Power_W=0.063, Supplier Part Number 1=541-49.9LCT-ND, TempCo="100 ppm/C", Tolerance_%=1, Value1=1%, Value2=0.063W, Value_Code=49R9, ValueDisplayed=49.9
R20: "RES, 21.0 k, 1%, 0.063 W, 0402", Manufacturer=Vishay-Dale, Power_W=0.063, Supplier Part Number 1=541-21.0KLCT-ND, TempCo="100 ppm/C", Tolerance_%=1, Value1=1%, Value2=0.063W, Value_Code=21k0, ValueDisplayed=21.0k
R21: "RES, 20.0 k, 1%, 0.063 W, 0402", Manufacturer=Vishay-Dale, Power_W=0.063, Supplier Part Number 1=541-20.0KLCT-ND, TempCo="100 ppm/C", Tolerance_%=1, Value1=1%, Value2=0.063W, Value_Code=20k0, ValueDisplayed=20.0k
R23: "RES, 2.00 k, 1%, 0.1 W, 0603", Manufacturer=Vishay-Dale, Power_W=0.1, Supplier Part Number 1=541-2.00KHCT-ND, TempCo="100 ppm/C", Tolerance_%=1, Value1=1%, Value2=0.1W, Value_Code=2k00, ValueDisplayed=2.00k
R24: "RES, 20.5 k, 1%, 0.063 W, 0402", Manufacturer=Vishay-Dale, Power_W=0.063, Supplier Part Number 1=541-20.5KLCT-ND, TempCo="100 ppm/C", Tolerance_%=1, Value1=1%, Value2=0.063W, Value_Code=20k5, ValueDisplayed=20.5k
R25: "RES, 20, 5%, 0.1 W, 0603", Manufacturer=Vishay-Dale, Power_W=0.1, Supplier Part Number 1=541-20GCT-ND, TempCo="200 ppm/C", Tolerance_%=5, Value1=5%, Value2=0.1W, Value_Code=20R0, ValueDisplayed=20
TP1 TP2: "Test Point, Miniature, Red, TH", Color=Red, Manufacturer=Keystone, Supplier Part Number 1=36-5000-ND
TP3: "Test Point, Miniature, White, TH", Color=White, Manufacturer=Keystone, Supplier Part Number 1=36-5002-ND
TP4: "Test Point, Miniature, Black, TH", Color=Black, Manufacturer=Keystone, Supplier Part Number 1=36-5001-ND
U1: "Smart Diode Controller, DGK0008A", Alternate Manufacturer="Texas Instruments"
U2: "5.5A Synchronous Buck Regulator for Automotive Applications, RNL0022A (VQFN-HR-22)", Alternate Manufacturer="Texas Instruments", Alternate PartNumber=LMS3655AQRNLTQ1
U3: "Automotive USB Charging Port Controller and Power Switch with Short to BAT protection, RVC0020A", Alternate Manufacturer="Texas Instruments", Alternate PartNumber=TPS254900IRVCTQ1
U4: "USMB Dedicated Charging Port Controller and Current Limiting Power Switch, DGN0008E", Alternate Manufacturer="Texas Instruments", Alternate PartNumber=TPS2511DGN
U5: "Dual Low Power Op Amp, D0008A", Alternate Manufacturer="Texas Instruments"
U6: library part TL431ACDBVRG4, "Adjustable Precision Shunt Regulator, 34 ppm / degC, 100 mA, 0 to 70 degC, 5-pin SOT-23 (DBV), Green (RoHS & no Sb/Br)", Alternate Manufacturer="Texas Instruments", Alternate PartNumber=Equivalent, Rating=Catalog, Supplier Part Number 1=TL431ACDBVRG4-ND, Temp Coeff(Max)(ppm/ degree C)=92, Temp Coeff(Typ)(ppm/ degree C)=34

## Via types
v1: diameter 20, hole 10, Top Layer to Bottom Layer, tented both sides, 99 vias
v2: diameter 19.68, hole 7.87, Top Layer to Bottom Layer, 6 vias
